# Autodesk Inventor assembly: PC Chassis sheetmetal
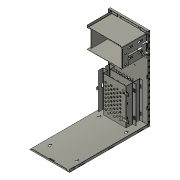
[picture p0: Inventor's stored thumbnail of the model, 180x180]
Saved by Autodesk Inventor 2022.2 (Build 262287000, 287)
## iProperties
Company: Autodesk Inc.
Created: 2006-09
Part Number: PC Chassis sheetmetal
Document SubType Name: Assembly
Designer: Autodesk Inc.
Mass: 1117.78 g
Surface Area: 13233.4 cm^2
Volume: 1117.78 cm^3
Density: 1 g/cm^3
Author: Autodesk Inc.
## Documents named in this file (7)
- D:\Inventor\Tutorial 2\第8回 シートメタルとネスティング\PC Chassis\PC Chassis sheetmetal.iam
- D:\Inventor\Tutorial 2\第8回 シートメタルとネスティング\PC Chassis\Bottom Bracket.ipt
- D:\Inventor\Tutorial 2\第8回 シートメタルとネスティング\PC Chassis\Front Bracket.ipt
- D:\Inventor\Tutorial 2\第8回 シートメタルとネスティング\PC Chassis\CDROM Bracket 01.ipt
- D:\Inventor\Tutorial 2\第8回 シートメタルとネスティング\PC Chassis\CDROM Bracket 02.ipt
- D:\Inventor\Tutorial 2\第8回 シートメタルとネスティング\PC Chassis\Hard Drive Bracket.ipt
- D:\Inventor\Tutorial 2\第8回 シートメタルとネスティング\PC Chassis\back support.ipt
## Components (7 placed, 6 different names)
1. Bottom Bracket:1 — Mate:2, Mate:49, Mate:52, Mate:56
2. Front Bracket:2 — Mate:2, Mate:41, Flush:5, Mate:42, Flush:6, Mate:56
3. CDROM Bracket 01:2 — Mate:42, Flush:6
4. CDROM Bracket 02:1 — Mate:41, Flush:5
5. Hard Drive Bracket:1 — Mate:51, Mate:52
6. Hard Drive Bracket:2 — Mate:49, Mate:51
7. back support:1
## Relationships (9: Mate 7, Flush 2)
- Mate:2: Bottom Bracket:1 ↔ Front Bracket:2
- Mate:41: Front Bracket:2 ↔ CDROM Bracket 02:1
- Flush:5: Front Bracket:2 ↔ CDROM Bracket 02:1
- Mate:42: Front Bracket:2 ↔ CDROM Bracket 01:2
- Flush:6: Front Bracket:2 ↔ CDROM Bracket 01:2
- Mate:49: Bottom Bracket:1 ↔ Hard Drive Bracket:2
- Mate:51: Hard Drive Bracket:1 ↔ Hard Drive Bracket:2
- Mate:52: Bottom Bracket:1 ↔ Hard Drive Bracket:1
- Mate:56: Bottom Bracket:1 ↔ Front Bracket:2
